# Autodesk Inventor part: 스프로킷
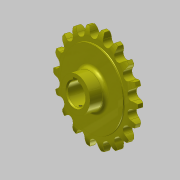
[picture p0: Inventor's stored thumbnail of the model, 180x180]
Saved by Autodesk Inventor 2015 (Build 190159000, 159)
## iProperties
Created: 2016-03
Part Number: 스프로킷
Material: 강철, 탄소
Document SubType Name: Modeling
Designer: mduedu
Density: 7.87 g/cm^3
Mass: 301.818 g
Surface Area: 124.882 cm^2
Volume: 38.3505 cm^3
Appearance: 노란색
Author: mduedu
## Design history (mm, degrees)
sketch "스케치1"
  geometry: L1 (0, 5)-(29.5, 5); L2 (29.5, 5)-(29.5, 4.1); L3 (30, 3.6)-(33.625, 3.6); L4 (40, 2)-(40, 0); L5 (40, 0)-(0, 0); L6 (0, 0)-(0, 5); L7 (0, -5)-(29.5, -5); L8 (29.5, -5)-(29.5, -4.1); L9 (30, -3.6)-(33.625, -3.6); L10 (40, -2)-(40, 0); L11 (0, 0)-(0, -5); A1 r 13.5 centre (33.625, -9.9) between (40, 2) and (33.625, 3.6); A2 r 13.5 centre (33.625, 9.9) between (33.625, -3.6) and (40, -2); A3 r 0.5 centre (30, 4.1) between (29.5, 4.1) and (30, 3.6); A4 r 0.5 centre (30, -4.1) between (30, -3.6) and (29.5, -4.1); 2 further points
  constraints: 22 end point, 8 point on circle, 6 symmetric about line, 5 tangent, 4 centre point, 4 parallel, 4 point on line, 1 equal radius, 1 horizontal, 1 perpendicular, 1 other
  dimensions: "d0" = 80 diameter of L4 L6; "d2" = 59 diameter of L2 L6; "d3" = 1.6 vertical distance of L4.start L3.end; "d4" = 3.6 distance from line of L4.end L3; "d5" = 5 distance between parallel lines of L5 L1; "d6" = 13.5 radius of A1; "d15" = 0.5 radius of A3
revolve "회전1" sketch "스케치1" stored, may be unused: angle "d7" = 90 deg
sketch "스케치2" dims "d8" = 65.2, "d11" = 80
  geometry: L1 (0, 0)-(0, 32.6); A1 r 36.57 centre (0, 0) between (-16.231, 32.771) and (0, 36.57); A2 r 3.97 centre (0, 36.57) between (-3.866, 35.665) and (0, 32.6); A3 r 12.7 centre (-16.231, 32.771) between (-3.866, 35.665) and (-5.534, 39.615); A4 r 12.7 centre (16.231, 32.771) between (5.534, 39.615) and (3.866, 35.665); A5 r 3.97 centre (0, 36.57) between (0, 32.6) and (3.866, 35.665); A6 r 40 centre (0, 0) between (5.534, 39.615) and (-5.534, 39.615); 2 further points
  constraints: 12 point on circle, 6 centre point, 4 coincident, 3 symmetric about line, 2 end point, 1 point on line, 1 tangent, 1 vertical, 1 vertical alignment, 7 other
  dimensions: "d10" = 73.14 diameter of A1; "d12" = 12.7 radius of A3
extrude "돌출1" cut sketch "스케치2" stored distance "d13" = 10; taper "d14" = 0 deg
sketch "스케치3"
  geometry: C1 r 13.5 at (0, 0); 1 further point
  constraints: 1 centre point, 1 coincident
  dimensions: "d19" = 27 diameter of C1
extrude "돌출2" join sketch "스케치3" distance "d20" = 13; taper "d21" = 0 deg
fillet "모깎기1" dims "d22" = 3
sketch "스케치4"
  geometry: L1 (-2.5, 0)-(2.5, 0); L2 (2.5, 0)-(2.5, 10.8); L3 (2.5, 10.8)-(-2.5, 10.8); L4 (-2.5, 10.8)-(-2.5, 0); C1 r 8.5 at (0, 0); 2 further points
  constraints: 8 end point, 2 coincident, 2 parallel, 1 centre point, 1 horizontal, 1 midpoint, 1 perpendicular
  dimensions: "d23" = 17 diameter of C1; "d25" = 5 distance of L2.end L3.end; "d26" = 10.8 distance of L1.end L2.end
extrude "돌출3" cut sketch "스케치4" stored distance "d27" = 8; taper "d28" = 0 deg
chamfer "모따기1" distance "d29" = 1; stored, may be unused: second distance "d30" = 2, angle "d31" = 45 deg
node "작업 평면1"
sketch "스케치5"
  geometry: L1 (13.5, 13)-(-13.5, 13) reference; 2 further points
  constraints: 1 vertical alignment
  dimensions: "d32" = 4 distance from line of point (0, 9) L1
hole "구멍1" sketch "스케치5" at (0, 9) diameter "d33" = 2.459; stored, may be unused: countersink angle "d37" = 90 deg, drill point angle "d39" = 118 deg; dims "d34" = 6, "d35" = 4, "d36" = 2, "d38" = 8
node "솔리드1"
pattern_circular "원형 패턴1" dims angle "d17" = 360 deg
